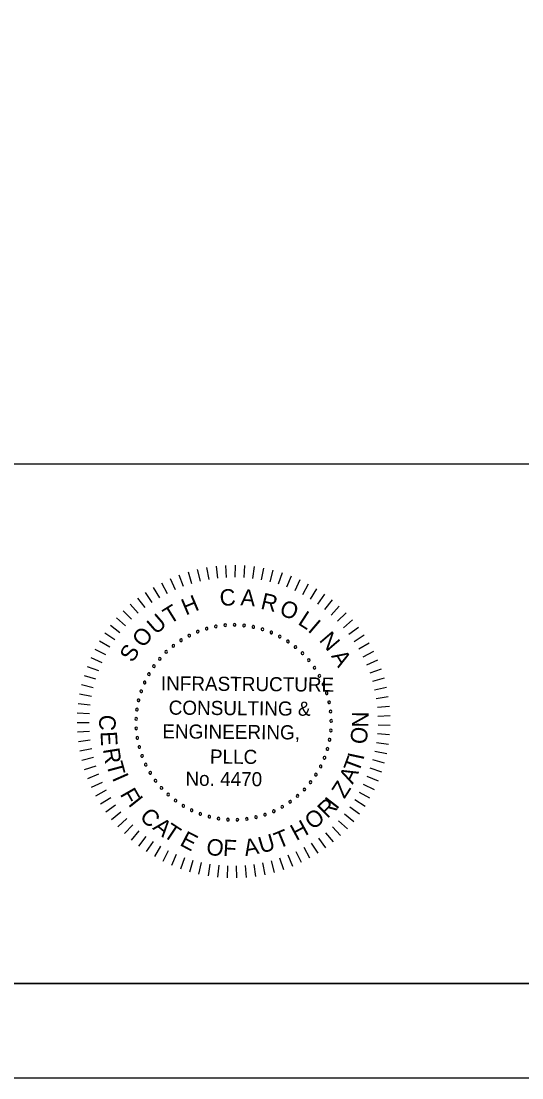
# Model space of a CAD drawing. Extents: x -125.5 to -89.4, y -5.1 to 16.9.
# Drawn here: x -100.32 to -97.68, y -5.07 to 0.53 of the extents above; entities that cross this region are included whole.
import ezdxf

# ---------------------------------------------------------------- set-up
doc = ezdxf.new("R2010")
doc.units = 0
for name, color, linetype in [('BR_BORDER LINES', 7, 'Continuous'), ('BR_TABLE LINES', 7, 'Continuous'), ('BR_TEXT', 7, 'Continuous'), ('Level 31', 7, 'Continuous')]:
    doc.layers.add(name, color=color, linetype=linetype)

msp = doc.modelspace()

# ---------------------------------------------------------------- linework, layer by layer
at = {"layer": 'BR_BORDER LINES'}
for p, q in [((-102.8989, -1.8161), (-97.5337, -1.8161)), ((-123.6994, -4.5662), (-90.0334, -4.5662))]:
    msp.add_line(p, q, dxfattribs=at)
at = {"layer": 'BR_TABLE LINES'}
msp.add_lwpolyline([(-123.6994, 16.4338), (-90.0334, 16.4338), (-90.0334, -4.5662), (-123.6994, -4.5662)], close=True, dxfattribs=at)
at = {"layer": 'BR_TEXT'}
for p, q in [((-99.489, -2.4048), (-99.4667, -2.4644)), ((-99.4412, -2.3886), (-99.4226, -2.4495)), ((-99.3925, -2.3754), (-99.3776, -2.4373)), ((-99.343, -2.3651), (-99.332, -2.4278)), ((-99.2931, -2.3579), (-99.2858, -2.4212)), ((-99.2427, -2.3538), (-99.2394, -2.4174)), ((-99.1923, -2.3527), (-99.1928, -2.4164)), ((-99.1418, -2.3548), (-99.1462, -2.4183)), ((-99.0916, -2.3599), (-99.0999, -2.423)), ((-99.0418, -2.368), (-99.0539, -2.4305)), ((-98.9925, -2.3792), (-99.0084, -2.4408)), ((-98.9441, -2.3933), (-98.9637, -2.4539)), ((-99.5813, -2.4457), (-99.5519, -2.5022)), ((-99.5358, -2.4238), (-99.5099, -2.482)), ((-98.8966, -2.4104), (-98.9199, -2.4696)), ((-98.8502, -2.4303), (-98.877, -2.488)), ((-98.8051, -2.453), (-98.8354, -2.509)), ((-99.6678, -2.4975), (-99.6318, -2.55)), ((-99.6253, -2.4703), (-99.5926, -2.5249)), ((-98.7615, -2.4785), (-98.7952, -2.5325)), ((-98.7195, -2.5065), (-98.7564, -2.5584)), ((-99.7475, -2.5595), (-99.7053, -2.6072)), ((-99.7086, -2.5273), (-99.6694, -2.5775)), ((-98.6793, -2.5371), (-98.7193, -2.5866)), ((-98.6411, -2.57), (-98.684, -2.617)), ((-99.7843, -2.5941), (-99.7393, -2.6391)), ((-98.6049, -2.6052), (-98.6506, -2.6495)), ((-99.8513, -2.6695), (-99.8012, -2.7087)), ((-99.819, -2.6308), (-99.7713, -2.673)), ((-98.571, -2.6426), (-98.6193, -2.684)), ((-98.5393, -2.6819), (-98.5901, -2.7204)), ((-99.8813, -2.7102), (-99.8288, -2.7463)), ((-98.5102, -2.7232), (-98.5632, -2.7584)), ((-99.9087, -2.7526), (-99.8541, -2.7854)), ((-98.4836, -2.7661), (-98.5387, -2.798)), ((-99.9555, -2.842), (-99.8973, -2.8679)), ((-99.9334, -2.7965), (-99.877, -2.826)), ((-98.4597, -2.8105), (-98.5166, -2.839)), ((-99.9747, -2.8886), (-99.9151, -2.911)), ((-98.4385, -2.8563), (-98.497, -2.8813)), ((-98.4202, -2.9034), (-98.4801, -2.9248)), ((-99.991, -2.9364), (-99.9302, -2.9551)), ((-98.4047, -2.9514), (-98.4659, -2.9691)), ((-100.0044, -2.9851), (-99.9426, -3)), ((-98.3922, -3.0004), (-98.4544, -3.0143)), ((-100.0149, -3.0345), (-99.9522, -3.0456)), ((-98.3828, -3.05), (-98.4456, -3.0601)), ((-100.0222, -3.0844), (-99.959, -3.0917)), ((-98.3763, -3.1), (-98.4397, -3.1063)), ((-100.0278, -3.1852), (-99.9641, -3.1847)), ((-100.0266, -3.1347), (-99.963, -3.1382)), ((-98.373, -3.1504), (-98.4366, -3.1528)), ((-100.026, -3.2356), (-99.9625, -3.2313)), ((-98.3727, -3.2009), (-98.4363, -3.1994)), ((-100.0211, -3.2859), (-99.9579, -3.2777)), ((-98.3813, -3.3014), (-98.4443, -3.2922)), ((-98.3755, -3.2513), (-98.4389, -3.2459)), ((-100.0131, -3.3357), (-99.9506, -3.3237)), ((-98.3902, -3.3511), (-98.4525, -3.3381)), ((-100.0021, -3.385), (-99.9405, -3.3692)), ((-98.4021, -3.4002), (-98.4635, -3.3834)), ((-99.9882, -3.4335), (-99.9276, -3.414)), ((-99.9713, -3.4811), (-99.912, -3.4579)), ((-98.417, -3.4484), (-98.4773, -3.4279)), ((-99.9515, -3.5276), (-99.8937, -3.5008)), ((-98.4554, -3.5417), (-98.5128, -3.514)), ((-98.4348, -3.4957), (-98.4937, -3.4715)), ((-99.929, -3.5727), (-99.8729, -3.5425)), ((-98.4789, -3.5865), (-98.5344, -3.5553)), ((-99.9037, -3.6164), (-99.8496, -3.5828)), ((-99.8758, -3.6585), (-99.8239, -3.6217)), ((-98.5336, -3.6712), (-98.5849, -3.6335)), ((-98.505, -3.6297), (-98.5585, -3.5952)), ((-99.8454, -3.6988), (-99.7958, -3.6589)), ((-98.5648, -3.7109), (-98.6137, -3.6702)), ((-99.8126, -3.7372), (-99.7655, -3.6943)), ((-99.7775, -3.7735), (-99.7331, -3.7278)), ((-98.6341, -3.7843), (-98.6777, -3.7379)), ((-98.5983, -3.7487), (-98.6447, -3.705)), ((-99.7403, -3.8076), (-99.6988, -3.7593)), ((-99.701, -3.8393), (-99.6626, -3.7886)), ((-98.7118, -3.8487), (-98.7494, -3.7974)), ((-98.672, -3.8177), (-98.7126, -3.7687)), ((-99.6599, -3.8687), (-99.6246, -3.8157)), ((-99.6171, -3.8954), (-99.5851, -3.8404)), ((-98.7967, -3.9032), (-98.8278, -3.8476)), ((-98.7534, -3.8772), (-98.7879, -3.8237)), ((-99.5728, -3.9195), (-99.5442, -3.8626)), ((-99.527, -3.9408), (-99.5019, -3.8823)), ((-99.48, -3.9594), (-99.4586, -3.8994)), ((-99.432, -3.975), (-99.4143, -3.9138)), ((-98.935, -3.9645), (-98.9555, -3.9042)), ((-98.8877, -3.9469), (-98.9118, -3.888)), ((-98.8416, -3.9264), (-98.8692, -3.8691)), ((-99.3832, -3.9876), (-99.3692, -3.9255)), ((-99.3336, -3.9973), (-99.3234, -3.9344)), ((-99.2836, -4.0039), (-99.2772, -3.9406)), ((-99.2332, -4.0075), (-99.2307, -3.9438)), ((-99.1827, -4.0079), (-99.1841, -3.9443)), ((-99.1323, -4.0053), (-99.1376, -3.9419)), ((-99.0821, -3.9997), (-99.0913, -3.9367)), ((-99.0324, -3.991), (-99.0454, -3.9286)), ((-98.9833, -3.9792), (-99.0001, -3.9178))]:
    msp.add_line(p, q, dxfattribs=at)
for centre, start, end in [((-99.3424, -2.6889), 16.1422, 196.1422), ((-99.2939, -2.6775), 10.6038, 190.6038), ((-99.2939, -2.6775), 190.6038, 10.6038), ((-99.2445, -2.6708), 5.0653, 185.0653), ((-99.2445, -2.6708), 185.0653, 5.0653), ((-99.1947, -2.6689), 359.5268, 179.5268), ((-99.1947, -2.6689), 179.5268, 359.5268), ((-99.145, -2.6718), 173.9884, 353.9884), ((-99.145, -2.6718), 353.9884, 173.9884), ((-99.0957, -2.6795), 168.4499, 348.4499), ((-99.0957, -2.6795), 348.4499, 168.4499), ((-99.435, -2.7255), 27.2191, 207.2191), ((-99.435, -2.7255), 207.2191, 27.2191), ((-99.3896, -2.705), 21.6807, 201.6807), ((-99.3896, -2.705), 201.6807, 21.6807), ((-99.3424, -2.6889), 196.1422, 16.1422), ((-99.0475, -2.6919), 162.9114, 342.9114), ((-99.0475, -2.6919), 342.9114, 162.9114), ((-99.0006, -2.709), 157.373, 337.373), ((-99.0006, -2.709), 337.373, 157.373), ((-98.9557, -2.7304), 151.8345, 331.8345), ((-98.9557, -2.7304), 331.8345, 151.8345), ((-99.5188, -2.7792), 38.2961, 218.2961), ((-99.5188, -2.7792), 218.2961, 38.2961), ((-99.4782, -2.7503), 32.7576, 212.7576), ((-99.4782, -2.7503), 212.7576, 32.7576), ((-98.913, -2.7561), 146.2961, 326.2961), ((-98.913, -2.7561), 326.2961, 146.2961), ((-98.873, -2.7858), 140.7576, 320.7576), ((-98.873, -2.7858), 320.7576, 140.7576), ((-99.5907, -2.848), 49.373, 229.373), ((-99.5907, -2.848), 229.373, 49.373), ((-99.5564, -2.8119), 43.8345, 223.8345), ((-99.5564, -2.8119), 223.8345, 43.8345), ((-98.836, -2.8192), 135.2191, 315.2191), ((-98.836, -2.8192), 315.2191, 135.2191), ((-98.8024, -2.8561), 129.6807, 309.6807), ((-98.8024, -2.8561), 309.6807, 129.6807), ((-99.6214, -2.8873), 54.9114, 234.9114), ((-99.6214, -2.8873), 234.9114, 54.9114), ((-98.7726, -2.896), 124.1422, 304.1422), ((-98.7726, -2.896), 304.1422, 124.1422), ((-99.6481, -2.9293), 60.4499, 240.4499), ((-99.6481, -2.9293), 240.4499, 60.4499), ((-98.7467, -2.9386), 118.6038, 298.6038), ((-98.7467, -2.9386), 298.6038, 118.6038), ((-99.6888, -3.0202), 71.5268, 251.5268), ((-99.6888, -3.0202), 251.5268, 71.5268), ((-99.6706, -2.9738), 65.9884, 245.9884), ((-99.6706, -2.9738), 245.9884, 65.9884), ((-98.7251, -2.9835), 113.0653, 293.0653), ((-98.7251, -2.9835), 293.0653, 113.0653), ((-99.7024, -3.0681), 77.0653, 257.0653), ((-99.7024, -3.0681), 257.0653, 77.0653), ((-98.7079, -3.0302), 107.5268, 287.5268), ((-98.7079, -3.0302), 287.5268, 107.5268), ((-98.6953, -3.0785), 101.9884, 281.9884), ((-98.6953, -3.0785), 281.9884, 101.9884), ((-99.7113, -3.1172), 82.6038, 262.6038), ((-99.7113, -3.1172), 262.6038, 82.6038), ((-98.6874, -3.1277), 96.4499, 276.4499), ((-98.6874, -3.1277), 276.4499, 96.4499), ((-99.7154, -3.1668), 88.1422, 268.1422), ((-99.7154, -3.1668), 268.1422, 88.1422), ((-98.6843, -3.1774), 90.9114, 270.9114), ((-98.6843, -3.1774), 270.9114, 90.9114), ((-99.7147, -3.2167), 93.6807, 273.6807), ((-99.7147, -3.2167), 273.6807, 93.6807), ((-98.686, -3.2272), 85.373, 265.373), ((-98.686, -3.2272), 265.373, 85.373), ((-99.7092, -3.2662), 99.2191, 279.2191), ((-99.7092, -3.2662), 279.2191, 99.2191), ((-98.6926, -3.2766), 79.8345, 259.8345), ((-98.6926, -3.2766), 259.8345, 79.8345), ((-99.6989, -3.3149), 104.7576, 284.7576), ((-99.6989, -3.3149), 284.7576, 104.7576), ((-99.684, -3.3625), 290.2961, 110.2961), ((-98.7038, -3.3251), 74.2961, 254.2961), ((-98.7038, -3.3251), 254.2961, 74.2961), ((-99.684, -3.3625), 110.2961, 290.2961), ((-99.6646, -3.4084), 115.8345, 295.8345), ((-99.6646, -3.4084), 295.8345, 115.8345), ((-98.7401, -3.4178), 63.2191, 243.2191), ((-98.7197, -3.3724), 68.7576, 248.7576), ((-98.7197, -3.3724), 248.7576, 68.7576), ((-99.6408, -3.4522), 121.373, 301.373), ((-99.6408, -3.4522), 301.373, 121.373), ((-98.7647, -3.4611), 57.6807, 237.6807), ((-98.7647, -3.4611), 237.6807, 57.6807), ((-98.7401, -3.4178), 243.2191, 63.2191), ((-99.6129, -3.4935), 126.9114, 306.9114), ((-99.6129, -3.4935), 306.9114, 126.9114), ((-98.7934, -3.5019), 52.1422, 232.1422), ((-98.7934, -3.5019), 232.1422, 52.1422), ((-99.5812, -3.5319), 132.4499, 312.4499), ((-99.5812, -3.5319), 312.4499, 132.4499), ((-99.5459, -3.5671), 137.9884, 317.9884), ((-99.5459, -3.5671), 317.9884, 137.9884), ((-98.862, -3.5741), 41.0653, 221.0653), ((-98.862, -3.5741), 221.0653, 41.0653), ((-98.826, -3.5396), 46.6038, 226.6038), ((-98.826, -3.5396), 226.6038, 46.6038), ((-99.5074, -3.5987), 143.5268, 323.5268), ((-99.5074, -3.5987), 323.5268, 143.5268), ((-99.466, -3.6264), 149.0653, 329.0653), ((-99.466, -3.6264), 329.0653, 149.0653), ((-98.9431, -3.6317), 29.9884, 209.9884), ((-98.9431, -3.6317), 209.9884, 29.9884), ((-98.9012, -3.6049), 35.5268, 215.5268), ((-98.9012, -3.6049), 215.5268, 35.5268), ((-99.4221, -3.65), 154.6038, 334.6038), ((-99.4221, -3.65), 334.6038, 154.6038), ((-99.3761, -3.6693), 160.1422, 340.1422), ((-99.3761, -3.6693), 340.1422, 160.1422), ((-99.3285, -3.684), 165.6807, 345.6807), ((-99.3285, -3.684), 345.6807, 165.6807), ((-99.2797, -3.6941), 351.2191, 171.2191), ((-99.1307, -3.6956), 7.8345, 187.8345), ((-99.0817, -3.6865), 13.373, 193.373), ((-99.0817, -3.6865), 193.373, 13.373), ((-99.0338, -3.6728), 18.9114, 198.9114), ((-99.0338, -3.6728), 198.9114, 18.9114), ((-98.9875, -3.6545), 24.4499, 204.4499), ((-98.9875, -3.6545), 204.4499, 24.4499), ((-99.2797, -3.6941), 171.2191, 351.2191), ((-99.2302, -3.6994), 356.7576, 176.7576), ((-99.2302, -3.6994), 176.7576, 356.7576), ((-99.1803, -3.6999), 2.2961, 182.2961), ((-99.1803, -3.6999), 182.2961, 2.2961), ((-99.1307, -3.6956), 187.8345, 7.8345)]:
    msp.add_arc(centre, 0.00701, start, end, dxfattribs=at)
at = {"layer": 'Level 31'}
msp.add_lwpolyline([(-125.5328, 16.9339), (-125.5328, -5.0661), (-89.5328, -5.0661), (-89.5328, 16.9339)], dxfattribs=at)

# ---------------------------------------------------------------- texts
at = {"layer": 'BR_TEXT'}
for s, height, rotation, p in [('H', 0.0872, 22.7882, (-99.453, -2.6197)), ('C', 0.0872, 4.7281, (-99.2702, -2.5703)), ('A', 0.0872, 355.6981, (-99.1657, -2.5654)), ('R', 0.0872, 346.6681, (-99.0615, -2.5824)), ('T', 0.0872, 31.8182, (-99.5379, -2.6674)), ('O', 0.0872, 337.638, (-98.9637, -2.6122)), ('U', 0.0872, 40.8482, (-99.6112, -2.7235)), ('L', 0.0872, 327.108, (-98.8649, -2.6626)), ('I', 0.0872, 319.578, (-98.8123, -2.7005)), ('O', 0.0872, 49.8782, (-99.6782, -2.7945)), ('N', 0.0872, 310.548, (-98.7515, -2.7512)), ('S', 0.0872, 58.9083, (-99.7336, -2.8727)), ('A', 0.0872, 301.5179, (-98.6864, -2.8336)), ('INFRASTRUCTURE', 0.074771, 359.5268, (-99.585, -3.0152)), ('CONSULTING &', 0.074771, 359.5268, (-99.5437, -3.1438)), ('C', 0.0872, 267.025, (-99.9086, -3.1426)), ('N', 0.0872, 89.2085, (-98.4872, -3.2124)), ('E', 0.0872, 273.025, (-99.9042, -3.2342)), ('ENGINEERING,', 0.074771, 359.5268, (-99.5773, -3.2693)), ('O', 0.0872, 83.2085, (-98.4982, -3.3038)), ('R', 0.0872, 279.025, (-99.8914, -3.3265)), ('PLLC', 0.07477, 359.5268, (-99.3256, -3.4028)), ('I', 0.0872, 77.9093, (-98.5137, -3.3881)), ('T', 0.0872, 285.025, (-99.874, -3.4053)), ('T', 0.0872, 69.3954, (-98.5394, -3.4556)), ('I', 0.0872, 293.7713, (-99.8443, -3.4784)), ('No. 4470', 0.07477, 359.5268, (-99.4551, -3.5197)), ('A', 0.0872, 63.3954, (-98.5702, -3.516)), ('Z', 0.0872, 57.3954, (-98.6141, -3.5923)), ('F', 0.0872, 299.7713, (-99.8031, -3.5644)), ('I', 0.0872, 308.5268, (-99.761, -3.6183)), ('R', 0.0872, 44.5268, (-98.7045, -3.6973)), ('I', 0.0872, 52.3339, (-98.6551, -3.65)), ('C', 0.0872, 314.5268, (-99.7017, -3.6884)), ('O', 0.0872, 38.5268, (-98.7811, -3.7572)), ('A', 0.0872, 320.5268, (-99.6325, -3.747)), ('T', 0.0872, 326.5268, (-99.5781, -3.7855)), ('H', 0.0872, 28.5268, (-98.8692, -3.8132)), ('E', 0.0872, 332.5268, (-99.4895, -3.8332)), ('O', 0.0872, 350.5268, (-99.3494, -3.8821)), ('A', 0.0872, 10.5268, (-99.138, -3.8929)), ('U', 0.0872, 16.5268, (-99.0541, -3.8794)), ('T', 0.0872, 22.5268, (-98.9624, -3.855)), ('F', 0.0872, 356.5268, (-99.2579, -3.8912))]:
    msp.add_text(s, height=height, rotation=rotation, dxfattribs=at).set_placement(p)

doc.saveas('drawing.dxf')
